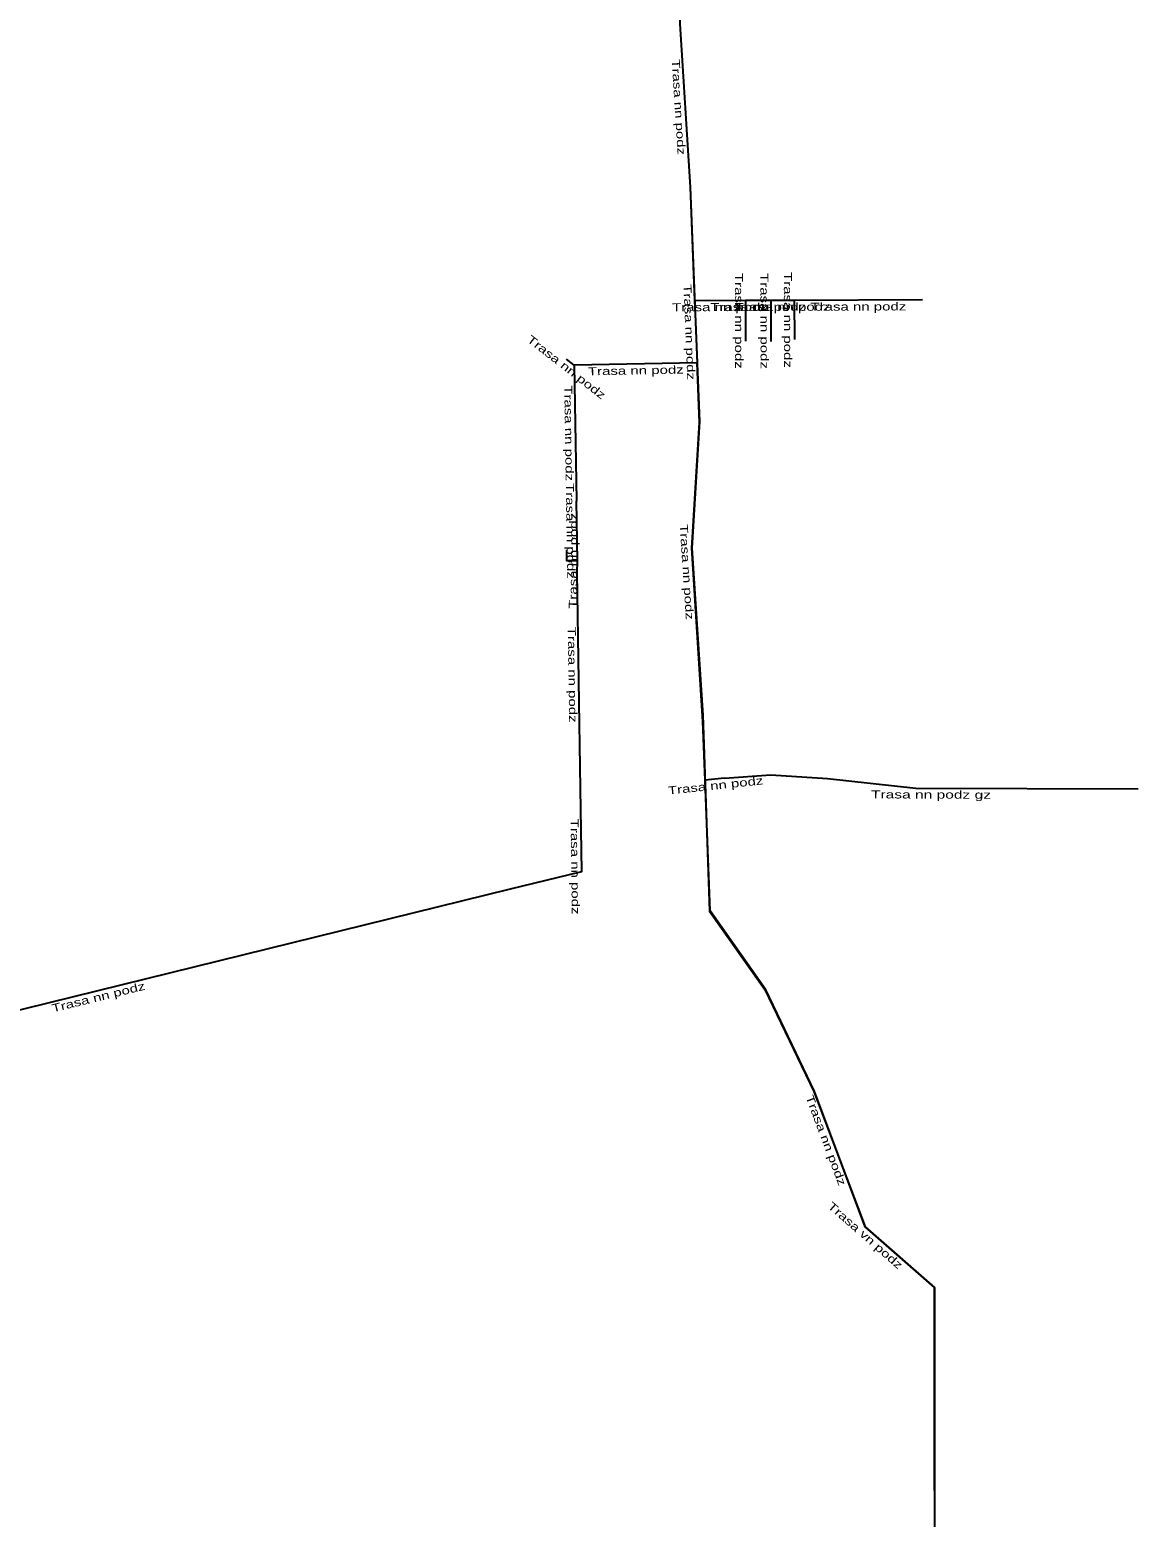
# Model space of a CAD drawing. Extents: x -810379 to -809541, y -1032744 to -1032173.
# Drawn here: x -810314.4 to -810245.2, y -1032427.9 to -1032334.9 of the extents above; entities that cross this region are included whole.
import ezdxf
from ezdxf.enums import TextEntityAlignment as Align

# ---------------------------------------------------------------- set-up
doc = ezdxf.new("R2010")
doc.units = 0
doc.header["$LTSCALE"] = 0.2
doc.layers.add('11', color=7, linetype='Continuous', lineweight=25)
doc.layers.add('21', color=7, linetype='Continuous', lineweight=25)
doc.layers.add('20', color=7, linetype='Continuous')

msp = doc.modelspace()

# ---------------------------------------------------------------- linework, layer by layer
at = {"layer": '11'}
for p, q in [((-810269.731, -1032351.864), (-810272.901, -1032351.876)), ((-810268.14, -1032351.857), (-810269.731, -1032351.864)), ((-810269.731, -1032351.864), (-810269.726, -1032354.391)), ((-810266.674, -1032351.852), (-810268.14, -1032351.857)), ((-810268.14, -1032351.857), (-810268.134, -1032354.419)), ((-810258.675, -1032351.821), (-810266.674, -1032351.852)), ((-810266.674, -1032351.852), (-810266.669, -1032354.294)), ((-810280.412, -1032355.903), (-810280.906, -1032355.516)), ((-810272.747, -1032355.752), (-810280.412, -1032355.903)), ((-810280.412, -1032355.903), (-810280.28, -1032364.381)), ((-810280.221, -1032368.114), (-810280.28, -1032364.381)), ((-810271.03, -1032381.694), (-810272.24, -1032381.826))]:
    msp.add_line(p, q, dxfattribs=at)
for points in [[(-810273.62, -1032327.623), (-810273.686, -1032329.588), (-810273.823, -1032334.563), (-810273.182, -1032344.772), (-810272.901, -1032351.876)], [(-810272.901, -1032351.876), (-810272.876, -1032352.679), (-810272.747, -1032355.752)], [(-810272.24, -1032381.826), (-810272.377, -1032378.167), (-810273.084, -1032367.327), (-810272.59, -1032359.484), (-810272.747, -1032355.752)], [(-810280.221, -1032368.114), (-810280.883, -1032368.132), (-810280.877, -1032367.443)], [(-810280.018, -1032382.347), (-810280.227, -1032368.844), (-810280.221, -1032368.114)], [(-810257.928, -1032426.203), (-810257.923, -1032413.534), (-810262.258, -1032409.728), (-810265.406, -1032401.281), (-810268.45, -1032394.929), (-810271.926, -1032389.991), (-810272.24, -1032381.826)], [(-810271.03, -1032381.694), (-810268.131, -1032381.491), (-810264.606, -1032381.729), (-810259.088, -1032382.322), (-810245.195, -1032382.36)], [(-810284.389, -1032388.621), (-810279.953, -1032387.528), (-810280.018, -1032382.347)], [(-810336.127, -1032401.121), (-810329.922, -1032399.845), (-810284.389, -1032388.621)]]:
    msp.add_lwpolyline(points, dxfattribs=at)
at = {"layer": '21'}
msp.add_lwpolyline([(-810273.823, -1032334.563), (-810273.182, -1032344.772), (-810272.876, -1032352.679), (-810272.59, -1032359.417), (-810273.084, -1032367.327), (-810272.392, -1032377.76), (-810271.976, -1032390.017), (-810268.521, -1032394.912), (-810265.461, -1032401.284), (-810262.258, -1032409.728), (-810257.923, -1032413.534), (-810257.928, -1032426.906), (-810257.93, -1032436.715)], dxfattribs=at)

# ---------------------------------------------------------------- texts
at = {"layer": '20'}
for s, rotation, width, p in [('Trasa nn podz', 273.593, 1.4, (-810274.145, -1032339.7918)), ('Trasa nn podz', 270.113, 1.4, (-810270.3778, -1032353.128)), ('Trasa nn podz', 270.134, 1.4, (-810268.7866, -1032353.1399)), ('Trasa nn podz', 270.117, 1.4, (-810267.3206, -1032353.074)), ('Trasa nn podz', 272.404, 1.4, (-810273.4771, -1032353.841)), ('Trasa nn podz', 0.217, 1.4, (-810271.3124, -1032352.5191)), ('Trasa nn podz', 0.252, 1.4, (-810268.9326, -1032352.5092)), ('Trasa nn podz', 0.195, 1.4, (-810267.4044, -1032352.5033)), ('Trasa nn podz', 0.222, 1.4, (-810262.6715, -1032352.4858)), ('Trasa nn podz', 321.925, 1.4, (-810281.0597, -1032356.2204)), ('Trasa nn podz', 1.129, 1.4, (-810276.5664, -1032356.4761)), ('Trasa nn podz', 270.892, 1.4, (-810280.9951, -1032360.1516)), ('Trasa nn podz', 270.905, 1.4, (-810280.8993, -1032366.2575)), ('Trasa nn podz', 89.501, 1.4, (-810280.2326, -1032368.1237)), ('Trasa nn podz', 273.732, 1.4, (-810273.6374, -1032368.8312)), ('Trasa nn podz', 270.887, 1.4, (-810280.7773, -1032375.2406)), ('Trasa nn podz', 6.226, 1.4, (-810271.5636, -1032382.406)), ('Trasa nn podz gz', 359.843, 1.45, (-810258.1372, -1032382.9746)), ('Trasa nn podz', 270.719, 1.4, (-810280.6066, -1032387.2294)), ('Trasa nn podz', 13.847, 1.4, (-810310.0753, -1032395.6218)), ('Trasa nn podz', 290.439, 1.4, (-810264.9324, -1032404.4112)), ('Trasa vn podz', 318.718, 1.4, (-810262.4074, -1032410.4603))]:
    msp.add_text(s, height=0.5, rotation=rotation, dxfattribs=dict(at, width=width)).set_placement(p, align=Align.CENTER)

doc.saveas('drawing.dxf')
